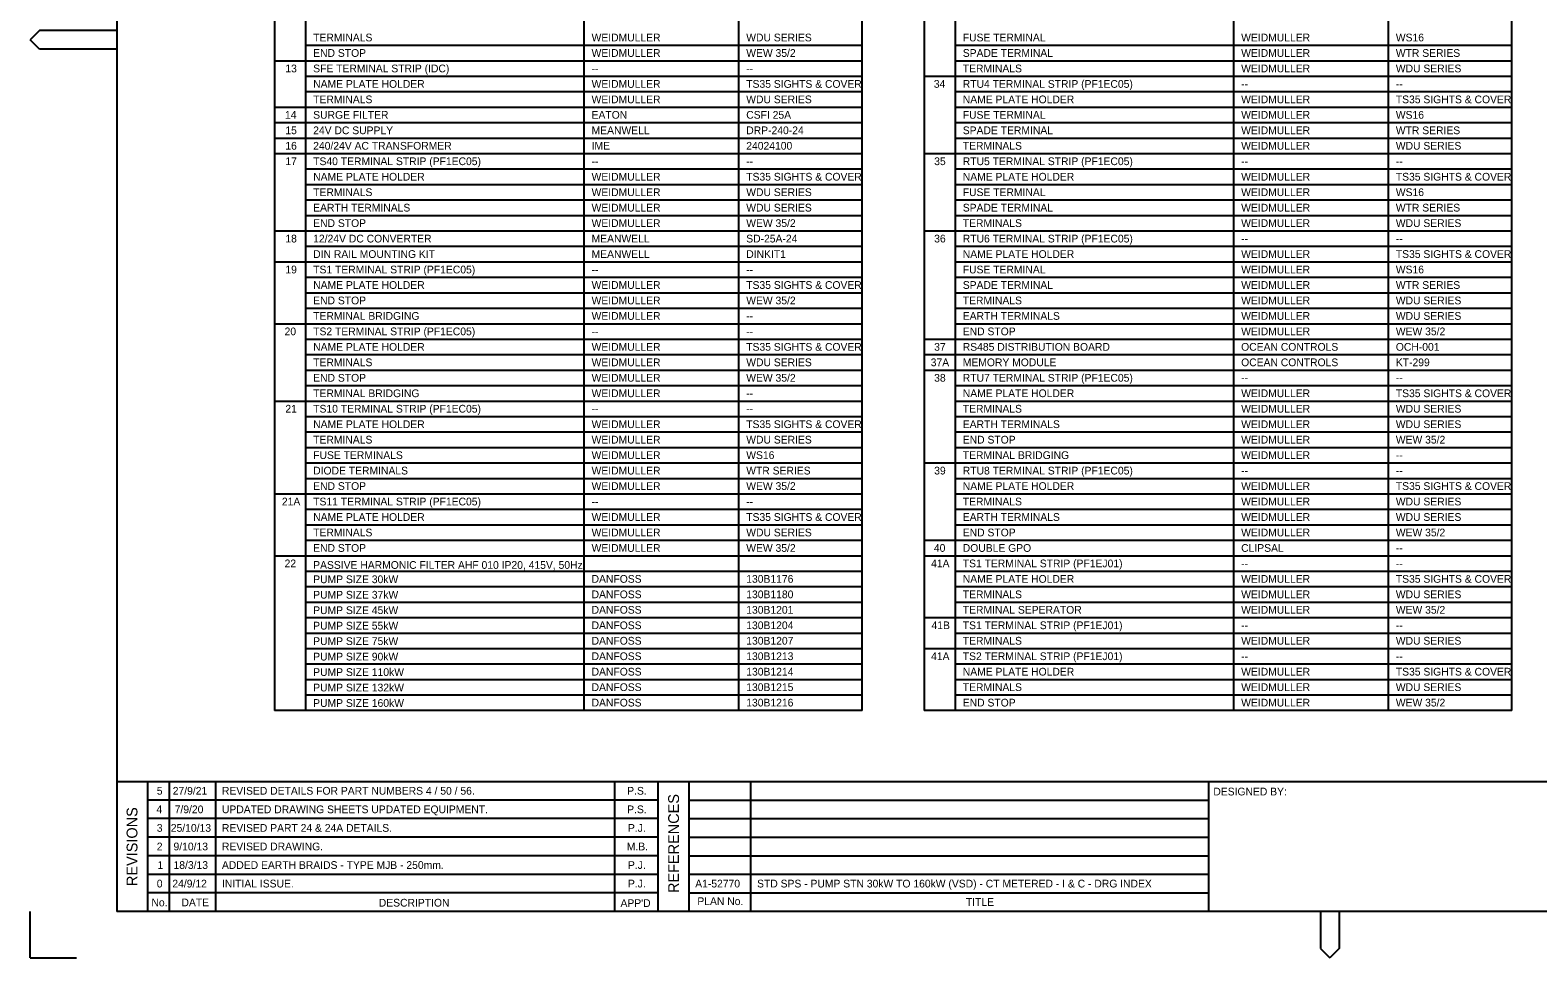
# Model space of a CAD drawing. Extents: x 841 to 1682, y 0 to 594.
# Drawn here: x 841 to 1328.4, y 0 to 299.9 of the extents above; entities that cross this region are included whole.
import ezdxf

# ---------------------------------------------------------------- set-up
doc = ezdxf.new("R2010")
doc.units = 0
doc.layers.add('A1BORDER', color=7, linetype='Continuous')
doc.layers.add('Level 1', color=7, linetype='Continuous')

msp = doc.modelspace()

# ---------------------------------------------------------------- linework, layer by layer
at = {"layer": 'A1BORDER'}
for p, q in [((869, 581), (869, 15)), ((844, 299.76), (841, 296.76)), ((869, 299.76), (844, 299.76)), ((844, 293.76), (841, 296.76)), ((869, 293.76), (844, 293.76)), ((869, 57), (1670, 57)), ((879, 15), (879, 57)), ((886, 15), (886, 57)), ((901, 15), (901, 57)), ((1030, 15), (1030, 57)), ((1044, 15), (1044, 57)), ((1054, 15), (1054, 57)), ((1074, 15), (1074, 57)), ((1222, 15), (1222, 57)), ((1044, 51), (879, 51)), ((1054, 51), (1222, 51)), ((1044, 45), (879, 45)), ((1054, 45), (1222, 45)), ((1044, 39), (879, 39)), ((1054, 39), (1222, 39)), ((1044, 33), (879, 33)), ((1054, 33), (1222, 33)), ((879, 27), (1044, 27)), ((1054, 27), (1222, 27)), ((1044, 21), (879, 21)), ((1054, 21), (1222, 21)), ((841, 0), (841, 15)), ((1670, 15), (869, 15)), ((1258.19, 15), (1258.19, 3)), ((1264.19, 15), (1264.19, 3)), ((841, 0), (856, 0)), ((1258.19, 3), (1261.19, 0)), ((1264.19, 3), (1261.19, 0))]:
    msp.add_line(p, q, dxfattribs=at)
at = {"layer": 'Level 1'}
for p, q in [((920, 568.5), (920, 80)), ((1110, 80), (1110, 568.5)), ((1130, 568.5), (1130, 80)), ((1320, 80), (1320, 568.5)), ((930, 558.75), (930, 80)), ((1020, 558.75), (1020, 80)), ((1070, 558.75), (1070, 80)), ((1140, 558.75), (1140, 80)), ((1230, 558.75), (1230, 80)), ((1280, 558.75), (1280, 80)), ((930, 295), (1110, 295)), ((1140, 295), (1320, 295)), ((920, 290), (1110, 290)), ((1140, 290), (1320, 290)), ((930, 285), (1110, 285)), ((1130, 285), (1320, 285)), ((930, 280), (1110, 280)), ((1140, 280), (1320, 280)), ((920, 275), (1110, 275)), ((1140, 275), (1320, 275)), ((920, 270), (1110, 270)), ((1140, 270), (1320, 270)), ((920, 265), (1110, 265)), ((1140, 265), (1320, 265)), ((920, 260), (1110, 260)), ((1130, 260), (1320, 260)), ((930, 255), (1110, 255)), ((1140, 255), (1320, 255)), ((930, 250), (1110, 250)), ((1140, 250), (1320, 250)), ((930, 245), (1110, 245)), ((1140, 245), (1320, 245)), ((930, 240), (1110, 240)), ((1140, 240), (1320, 240)), ((920, 235), (1110, 235)), ((1130, 235), (1320, 235)), ((930, 230), (1110, 230)), ((1140, 230), (1320, 230)), ((920, 225), (1110, 225)), ((1140, 225), (1320, 225)), ((930, 220), (1110, 220)), ((1140, 220), (1320, 220)), ((930, 215), (1110, 215)), ((1140, 215), (1320, 215)), ((930, 210), (1110, 210)), ((1140, 210), (1320, 210)), ((920, 205), (1110, 205)), ((1140, 205), (1320, 205)), ((930, 200), (1110, 200)), ((1130, 200), (1320, 200)), ((930, 195), (1110, 195)), ((1130, 195), (1320, 195)), ((930, 190), (1110, 190)), ((1130, 190), (1320, 190)), ((930, 185), (1110, 185)), ((1140, 185), (1320, 185)), ((920, 180), (1110, 180)), ((1140, 180), (1320, 180)), ((930, 175), (1110, 175)), ((1140, 175), (1320, 175)), ((930, 170), (1110, 170)), ((1140, 170), (1320, 170)), ((930, 165), (1110, 165)), ((1140, 165), (1320, 165)), ((930, 160), (1110, 160)), ((1130, 160), (1320, 160)), ((930, 155), (1110, 155)), ((1140, 155), (1320, 155)), ((920, 150), (1110, 150)), ((1140, 150), (1320, 150)), ((930, 145), (1110, 145)), ((1140, 145), (1320, 145)), ((930, 140), (1110, 140)), ((1140, 140), (1320, 140)), ((930, 135), (1110, 135)), ((1130, 135), (1320, 135)), ((920, 130), (1110, 130)), ((1130, 130), (1320, 130)), ((930, 125), (1110, 125)), ((1140, 125), (1320, 125)), ((930, 120), (1110, 120)), ((1140, 120), (1320, 120)), ((930, 115), (1110, 115)), ((1140, 115), (1320, 115)), ((930, 110), (1110, 110)), ((1130, 110), (1320, 110)), ((930, 105), (1110, 105)), ((1140, 105), (1320, 105)), ((930, 100), (1110, 100)), ((1130, 100), (1320, 100)), ((930, 95), (1110, 95)), ((1140, 95), (1320, 95)), ((930, 90), (1110, 90)), ((1140, 90), (1320, 90)), ((930, 85), (1110, 85)), ((1140, 85), (1320, 85)), ((1110, 80), (920, 80)), ((1320, 80), (1130, 80))]:
    msp.add_line(p, q, dxfattribs=at)

# ---------------------------------------------------------------- texts
at = {"layer": 'A1BORDER'}
for s, height, p in [('DESIGNED BY:', 2.5, (1223.5, 52.5)), ('PLAN No.', 2.5, (1056.69, 17.06)), ('No.', 2.5, (880.21, 16.65)), ('DATE', 2.5, (889.92, 16.65)), ('DESCRIPTION', 2.50002, (953.71, 16.57)), ("APP'D", 2.5, (1031.85, 16.44)), ('TITLE', 2.5, (1143.5, 16.81))]:
    msp.add_text(s, height=height, dxfattribs=at).set_placement(p)
for s, p in [('REFERENCES', (1050.76, 20.96)), ('REVISIONS', (875.68, 23.2))]:
    msp.add_text(s, height=3.5, rotation=90, dxfattribs=at).set_placement(p)
at = {"layer": 'Level 1'}
for s, height, p in [('TERMINALS', 2.5, (932.5, 296.25)), ('WEIDMULLER', 2.5, (1022.5, 296.25)), ('WDU SERIES', 2.5, (1072.5, 296.25)), ('FUSE TERMINAL', 2.5, (1142.5, 296.25)), ('WEIDMULLER', 2.5, (1232.5, 296.25)), ('WS16', 2.5, (1282.5, 296.25)), ('END STOP', 2.5, (932.5, 291.25)), ('WEIDMULLER', 2.5, (1022.5, 291.25)), ('WEW 35/2', 2.5, (1072.5, 291.25)), ('SPADE TERMINAL', 2.5, (1142.5, 291.25)), ('WEIDMULLER', 2.5, (1232.5, 291.25)), ('WTR SERIES', 2.5, (1282.5, 291.25)), ('13', 2.5, (923.506, 286.25)), ('SFE TERMINAL STRIP (IDC)', 2.5, (932.5, 286.25)), ('TERMINALS', 2.5, (1142.5, 286.25)), ('WEIDMULLER', 2.5, (1232.5, 286.25)), ('WDU SERIES', 2.5, (1282.5, 286.25)), ('NAME PLATE HOLDER', 2.5, (932.5, 281.25)), ('WEIDMULLER', 2.5, (1022.5, 281.25)), ('--', 2.5, (1022.5, 286.25)), ('TS35 SIGHTS & COVER', 2.5, (1072.5, 281.25)), ('--', 2.5, (1072.5, 286.25)), ('34', 2.5, (1133.132, 281.25)), ('RTU4 TERMINAL STRIP (PF1EC05)', 2.5, (1142.5, 281.25)), ('TERMINALS', 2.5, (932.5, 276.25)), ('WEIDMULLER', 2.5, (1022.5, 276.25)), ('WDU SERIES', 2.5, (1072.5, 276.25)), ('NAME PLATE HOLDER', 2.5, (1142.5, 276.25)), ('WEIDMULLER', 2.5, (1232.5, 276.25)), ('--', 2.5, (1232.5, 281.25)), ('TS35 SIGHTS & COVER', 2.5, (1282.5, 276.25)), ('--', 2.5, (1282.5, 281.25)), ('14', 2.5, (923.381, 271.25)), ('SURGE FILTER', 2.5, (932.5, 271.25)), ('EATON', 2.5, (1022.5, 271.25)), ('CSFI 25A', 2.5, (1072.5, 271.25)), ('FUSE TERMINAL', 2.5, (1142.5, 271.25)), ('WEIDMULLER', 2.5, (1232.5, 271.25)), ('WS16', 2.5, (1282.5, 271.25)), ('15', 2.5, (923.506, 266.25)), ('24V DC SUPPLY', 2.5, (932.5, 266.25)), ('MEANWELL', 2.5, (1022.5, 266.25)), ('DRP-240-24', 2.5, (1072.5, 266.25)), ('SPADE TERMINAL', 2.5, (1142.5, 266.25)), ('WEIDMULLER', 2.5, (1232.5, 266.25)), ('WTR SERIES', 2.5, (1282.5, 266.25)), ('16', 2.5, (923.506, 261.25)), ('240/24V AC TRANSFORMER', 2.5, (932.5, 261.25)), ('IME', 2.5, (1022.5, 261.25)), ('24024100', 2.5, (1072.5, 261.25)), ('TERMINALS', 2.5, (1142.5, 261.25)), ('WEIDMULLER', 2.5, (1232.5, 261.25)), ('WDU SERIES', 2.5, (1282.5, 261.25)), ('17', 2.5, (923.506, 256.25)), ('TS40 TERMINAL STRIP (PF1EC05)', 2.5, (932.5, 256.25)), ('35', 2.5, (1133.257, 256.25)), ('RTU5 TERMINAL STRIP (PF1EC05)', 2.5, (1142.5, 256.25)), ('NAME PLATE HOLDER', 2.5, (932.5, 251.25)), ('WEIDMULLER', 2.5, (1022.5, 251.25)), ('--', 2.5, (1022.5, 256.25)), ('TS35 SIGHTS & COVER', 2.5, (1072.5, 251.25)), ('--', 2.5, (1072.5, 256.25)), ('NAME PLATE HOLDER', 2.5, (1142.5, 251.25)), ('WEIDMULLER', 2.5, (1232.5, 251.25)), ('--', 2.5, (1232.5, 256.25)), ('TS35 SIGHTS & COVER', 2.5, (1282.5, 251.25)), ('--', 2.5, (1282.5, 256.25)), ('TERMINALS', 2.5, (932.5, 246.25)), ('WEIDMULLER', 2.5, (1022.5, 246.25)), ('WDU SERIES', 2.5, (1072.5, 246.25)), ('FUSE TERMINAL', 2.5, (1142.5, 246.25)), ('WEIDMULLER', 2.5, (1232.5, 246.25)), ('WS16', 2.5, (1282.5, 246.25)), ('EARTH TERMINALS', 2.5, (932.5, 241.25)), ('WEIDMULLER', 2.5, (1022.5, 241.25)), ('WDU SERIES', 2.5, (1072.5, 241.25)), ('SPADE TERMINAL', 2.5, (1142.5, 241.25)), ('WEIDMULLER', 2.5, (1232.5, 241.25)), ('WTR SERIES', 2.5, (1282.5, 241.25)), ('WEW 35/2', 2.5, (1072.5, 236.25)), ('END STOP', 2.5, (932.5, 236.25)), ('WEIDMULLER', 2.5, (1022.5, 236.25)), ('TERMINALS', 2.5, (1142.5, 236.25)), ('WEIDMULLER', 2.5, (1232.5, 236.25)), ('WDU SERIES', 2.5, (1282.5, 236.25)), ('18', 2.5, (923.506, 231.25)), ('12/24V DC CONVERTER', 2.5, (932.5, 231.25)), ('MEANWELL', 2.5, (1022.5, 231.25)), ('SD-25A-24', 2.5, (1072.5, 231.25)), ('36', 2.5, (1133.257, 231.25)), ('RTU6 TERMINAL STRIP (PF1EC05)', 2.5, (1142.5, 231.25)), ('--', 2.5, (1232.5, 231.25)), ('--', 2.5, (1282.5, 231.25)), ('DIN RAIL MOUNTING KIT', 2.5, (932.5, 226.25)), ('MEANWELL', 2.5, (1022.5, 226.25)), ('DINKIT1', 2.5, (1072.5, 226.25)), ('NAME PLATE HOLDER', 2.5, (1142.5, 226.25)), ('WEIDMULLER', 2.5, (1232.5, 226.25)), ('TS35 SIGHTS & COVER', 2.5, (1282.5, 226.25)), ('19', 2.5, (923.506, 221.25)), ('TS1 TERMINAL STRIP (PF1EC05)', 2.5, (932.5, 221.25)), ('--', 2.5, (1022.5, 221.25)), ('--', 2.5, (1072.5, 221.25)), ('FUSE TERMINAL', 2.5, (1142.5, 221.25)), ('WEIDMULLER', 2.5, (1232.5, 221.25)), ('WS16', 2.5, (1282.5, 221.25)), ('NAME PLATE HOLDER', 2.5, (932.5, 216.25)), ('WEIDMULLER', 2.5, (1022.5, 216.25)), ('TS35 SIGHTS & COVER', 2.5, (1072.5, 216.25)), ('SPADE TERMINAL', 2.5, (1142.5, 216.25)), ('WEIDMULLER', 2.5, (1232.5, 216.25)), ('WTR SERIES', 2.5, (1282.5, 216.25)), ('END STOP', 2.5, (932.5, 211.25)), ('WEIDMULLER', 2.5, (1022.5, 211.25)), ('WEW 35/2', 2.5, (1072.5, 211.25)), ('TERMINALS', 2.5, (1142.5, 211.25)), ('WEIDMULLER', 2.5, (1232.5, 211.25)), ('WDU SERIES', 2.5, (1282.5, 211.25)), ('TERMINAL BRIDGING', 2.5, (932.5, 206.25)), ('WEIDMULLER', 2.5, (1022.5, 206.25)), ('--', 2.5, (1072.5, 206.25)), ('EARTH TERMINALS', 2.5, (1142.5, 206.25)), ('WEIDMULLER', 2.5, (1232.5, 206.25)), ('WDU SERIES', 2.5, (1282.5, 206.25)), ('20', 2.5, (923.257, 201.25)), ('TS2 TERMINAL STRIP (PF1EC05)', 2.5, (932.5, 201.25)), ('--', 2.5, (1022.5, 201.25)), ('--', 2.5, (1072.5, 201.25)), ('END STOP', 2.5, (1142.5, 201.25)), ('WEIDMULLER', 2.5, (1232.5, 201.25)), ('WEW 35/2', 2.5, (1282.5, 201.25)), ('NAME PLATE HOLDER', 2.5, (932.5, 196.25)), ('WEIDMULLER', 2.5, (1022.5, 196.25)), ('TS35 SIGHTS & COVER', 2.5, (1072.5, 196.25)), ('37', 2.5, (1133.257, 196.25)), ('RS485 DISTRIBUTION BOARD', 2.5, (1142.5, 196.25)), ('OCEAN CONTROLS', 2.5, (1232.5, 196.25)), ('OCH-001', 2.5, (1282.5, 196.25)), ('TERMINALS', 2.5, (932.5, 191.25)), ('WEIDMULLER', 2.5, (1022.5, 191.25)), ('WDU SERIES', 2.5, (1072.5, 191.25)), ('37A', 2.5, (1132.136, 191.25)), ('MEMORY MODULE', 2.5, (1142.5, 191.25)), ('OCEAN CONTROLS', 2.5, (1232.5, 191.25)), ('KT-299', 2.5, (1282.5, 191.25)), ('END STOP', 2.5, (932.5, 186.25)), ('WEIDMULLER', 2.5, (1022.5, 186.25)), ('WEW 35/2', 2.5, (1072.5, 186.25)), ('38', 2.5, (1133.257, 186.25)), ('RTU7 TERMINAL STRIP (PF1EC05)', 2.5, (1142.5, 186.25)), ('--', 2.5, (1232.5, 186.25)), ('--', 2.5, (1282.5, 186.25)), ('TERMINAL BRIDGING', 2.5, (932.5, 181.25)), ('WEIDMULLER', 2.5, (1022.5, 181.25)), ('--', 2.5, (1072.5, 181.25)), ('NAME PLATE HOLDER', 2.5, (1142.5, 181.25)), ('WEIDMULLER', 2.5, (1232.5, 181.25)), ('TS35 SIGHTS & COVER', 2.5, (1282.5, 181.25)), ('21', 2.5, (923.506, 176.25)), ('TS10 TERMINAL STRIP (PF1EC05)', 2.5, (932.5, 176.25)), ('--', 2.5, (1022.5, 176.25)), ('--', 2.5, (1072.5, 176.25)), ('TERMINALS', 2.5, (1142.5, 176.25)), ('WEIDMULLER', 2.5, (1232.5, 176.25)), ('WDU SERIES', 2.5, (1282.5, 176.25)), ('NAME PLATE HOLDER', 2.5, (932.5, 171.25)), ('WEIDMULLER', 2.5, (1022.5, 171.25)), ('TS35 SIGHTS & COVER', 2.5, (1072.5, 171.25)), ('EARTH TERMINALS', 2.5, (1142.5, 171.25)), ('WEIDMULLER', 2.5, (1232.5, 171.25)), ('WDU SERIES', 2.5, (1282.5, 171.25)), ('TERMINALS', 2.5, (932.5, 166.25)), ('WEIDMULLER', 2.5, (1022.5, 166.25)), ('WDU SERIES', 2.5, (1072.5, 166.25)), ('END STOP', 2.5, (1142.5, 166.25)), ('WEIDMULLER', 2.5, (1232.5, 166.25)), ('WEW 35/2', 2.5, (1282.5, 166.25)), ('FUSE TERMINALS', 2.5, (932.5, 161.25)), ('WEIDMULLER', 2.5, (1022.5, 161.25)), ('WS16', 2.5, (1072.5, 161.25)), ('TERMINAL BRIDGING', 2.5, (1142.5, 161.25)), ('WEIDMULLER', 2.5, (1232.5, 161.25)), ('--', 2.5, (1282.5, 161.25)), ('DIODE TERMINALS', 2.5, (932.5, 156.25)), ('WEIDMULLER', 2.5, (1022.5, 156.25)), ('WTR SERIES', 2.5, (1072.5, 156.25)), ('39', 2.5, (1133.257, 156.25)), ('RTU8 TERMINAL STRIP (PF1EC05)', 2.5, (1142.5, 156.25)), ('--', 2.5, (1232.5, 156.25)), ('--', 2.5, (1282.5, 156.25)), ('END STOP', 2.5, (932.5, 151.25)), ('WEIDMULLER', 2.5, (1022.5, 151.25)), ('WEW 35/2', 2.5, (1072.5, 151.25)), ('NAME PLATE HOLDER', 2.5, (1142.5, 151.25)), ('WEIDMULLER', 2.5, (1232.5, 151.25)), ('TS35 SIGHTS & COVER', 2.5, (1282.5, 151.25)), ('21A', 2.5, (922.385, 146.25)), ('TS11 TERMINAL STRIP (PF1EC05)', 2.5, (932.5, 146.25)), ('--', 2.5, (1022.5, 146.25)), ('--', 2.5, (1072.5, 146.25)), ('TERMINALS', 2.5, (1142.5, 146.25)), ('WEIDMULLER', 2.5, (1232.5, 146.25)), ('WDU SERIES', 2.5, (1282.5, 146.25)), ('NAME PLATE HOLDER', 2.5, (932.5, 141.25)), ('WEIDMULLER', 2.5, (1022.5, 141.25)), ('TS35 SIGHTS & COVER', 2.5, (1072.5, 141.25)), ('EARTH TERMINALS', 2.5, (1142.5, 141.25)), ('WEIDMULLER', 2.5, (1232.5, 141.25)), ('WDU SERIES', 2.5, (1282.5, 141.25)), ('TERMINALS', 2.5, (932.5, 136.25)), ('WEIDMULLER', 2.5, (1022.5, 136.25)), ('WDU SERIES', 2.5, (1072.5, 136.25)), ('END STOP', 2.5, (1142.5, 136.25)), ('WEIDMULLER', 2.5, (1232.5, 136.25)), ('WEW 35/2', 2.5, (1282.5, 136.25)), ('END STOP', 2.5, (932.5, 131.25)), ('WEIDMULLER', 2.5, (1022.5, 131.25)), ('WEW 35/2', 2.5, (1072.5, 131.25)), ('40', 2.5, (1133.164, 131.25)), ('DOUBLE GPO', 2.5, (1142.5, 131.25)), ('CLIPSAL', 2.5, (1232.5, 131.25)), ('--', 2.5, (1282.5, 131.25)), ('22', 2.5, (923.257, 126.25)), ('PASSIVE HARMONIC FILTER AHF 010 IP20, 415V, 50Hz', 2.5, (932.5, 125.75)), ('41A', 2.5, (1132.261, 126.25)), ('TS1 TERMINAL STRIP (PF1EJ01)', 2.5, (1142.5, 126.25)), ('--', 2.5, (1232.5, 126.25)), ('--', 2.5, (1282.5, 126.25)), ('PUMP SIZE 30kW', 2.5, (932.5, 121.125)), ('DANFOSS', 2.5, (1022.5, 121.25)), ('130B1176', 2.5, (1072.5, 121.25)), ('NAME PLATE HOLDER', 2.5, (1142.5, 121.25)), ('WEIDMULLER', 2.5, (1232.5, 121.25)), ('TS35 SIGHTS & COVER', 2.5, (1282.5, 121.25)), ('PUMP SIZE 37kW', 2.5, (932.5, 116.125)), ('DANFOSS', 2.5, (1022.5, 116.25)), ('130B1180', 2.5, (1072.5, 116.25)), ('TERMINALS', 2.5, (1142.5, 116.25)), ('WEIDMULLER', 2.5, (1232.5, 116.25)), ('WDU SERIES', 2.5, (1282.5, 116.25)), ('PUMP SIZE 45kW', 2.5, (932.5, 111.125)), ('DANFOSS', 2.5, (1022.5, 111.25)), ('130B1201', 2.5, (1072.5, 111.25)), ('TERMINAL SEPERATOR', 2.5, (1142.5, 111.25)), ('WEIDMULLER', 2.5, (1232.5, 111.25)), ('WEW 35/2', 2.5, (1282.5, 111.25)), ('PUMP SIZE 55kW', 2.5, (932.5, 106.125)), ('DANFOSS', 2.5, (1022.5, 106.25)), ('130B1204', 2.5, (1072.5, 106.25)), ('41B', 2.5, (1132.385, 106.25)), ('TS1 TERMINAL STRIP (PF1EJ01)', 2.5, (1142.5, 106.25)), ('--', 2.5, (1232.5, 106.25)), ('--', 2.5, (1282.5, 106.25)), ('PUMP SIZE 75kW', 2.5, (932.5, 101.125)), ('DANFOSS', 2.5, (1022.5, 101.25)), ('130B1207', 2.5, (1072.5, 101.25)), ('TERMINALS', 2.5, (1142.5, 101.25)), ('WEIDMULLER', 2.5, (1232.5, 101.25)), ('WDU SERIES', 2.5, (1282.5, 101.25)), ('PUMP SIZE 90kW', 2.5, (932.5, 96.125)), ('DANFOSS', 2.5, (1022.5, 96.25)), ('130B1213', 2.5, (1072.5, 96.25)), ('41A', 2.5, (1132.261, 96.25)), ('TS2 TERMINAL STRIP (PF1EJ01)', 2.5, (1142.5, 96.25)), ('PUMP SIZE 110kW', 2.5, (932.5, 91.125)), ('DANFOSS', 2.5, (1022.5, 91.25)), ('130B1214', 2.5, (1072.5, 91.25)), ('NAME PLATE HOLDER', 2.5, (1142.5, 91.25)), ('WEIDMULLER', 2.5, (1232.5, 91.25)), ('--', 2.5, (1232.5, 96.25)), ('TS35 SIGHTS & COVER', 2.5, (1282.5, 91.25)), ('--', 2.5, (1282.5, 96.25)), ('PUMP SIZE 132kW', 2.5, (932.5, 86.125)), ('DANFOSS', 2.5, (1022.5, 86.25)), ('130B1215', 2.5, (1072.5, 86.25)), ('TERMINALS', 2.5, (1142.5, 86.25)), ('WEIDMULLER', 2.5, (1232.5, 86.25)), ('WDU SERIES', 2.5, (1282.5, 86.25)), ('PUMP SIZE 160kW', 2.5, (932.5, 81.125)), ('DANFOSS', 2.5, (1022.5, 81.25)), ('130B1216', 2.5, (1072.5, 81.25)), ('END STOP', 2.5, (1142.5, 81.25)), ('WEIDMULLER', 2.5, (1232.5, 81.25)), ('WEW 35/2', 2.5, (1282.5, 81.25)), ('5', 2.5, (881.94, 52.75)), ('27/9/21', 2.5, (887.094, 52.75)), ('REVISED DETAILS FOR PART NUMBERS 4 / 50 / 56.', 2.50002, (903, 52.75)), ('P.S.', 2.5, (1034.015, 52.75)), ('4', 2.5, (881.815, 46.75)), ('7/9/20', 2.5, (887.716, 46.75)), ('UPDATED DRAWING SHEETS UPDATED EQUIPMENT.', 2.50002, (903, 46.75)), ('P.S.', 2.5, (1034.015, 46.75)), ('3', 2.5, (881.94, 40.75)), ('25/10/13', 2.5, (886.471, 40.75)), ('REVISED PART 24 & 24A DETAILS.', 2.50002, (903, 40.75)), ('P.J.', 2.5, (1034.265, 40.75)), ('2', 2.5, (881.94, 34.75)), ('9/10/13', 2.5, (887.343, 34.75)), ('REVISED DRAWING.', 2.50002, (903, 34.75)), ('M.B.', 2.5, (1033.891, 34.75)), ('1', 2.5, (882.189, 28.75)), ('18/3/13', 2.5, (887.343, 28.75)), ('ADDED EARTH BRAIDS - TYPE MJB - 250mm.', 2.50002, (903, 28.75)), ('P.J.', 2.5, (1034.265, 28.75)), ('0', 2.5, (881.94, 22.75)), ('24/9/12', 2.5, (886.969, 22.75)), ('INITIAL ISSUE.', 2.50002, (903, 22.75)), ('P.J.', 2.5, (1034.265, 22.75)), ('A1-52770', 2.5, (1056, 22.75)), ('STD SPS - PUMP STN 30kW TO 160kW (VSD) - CT METERED - I & C - DRG INDEX', 2.50002, (1076, 22.75))]:
    msp.add_text(s, height=height, dxfattribs=at).set_placement(p)

doc.saveas('drawing.dxf')
